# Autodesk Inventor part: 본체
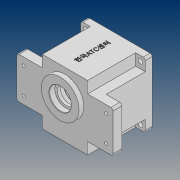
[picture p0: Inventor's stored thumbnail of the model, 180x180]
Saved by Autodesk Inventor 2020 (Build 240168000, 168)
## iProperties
Created: 2020-07
Part Number: 본체
Material: 일반
Document SubType Name: Modeling
Designer: PC312-
Density: 1 g/cm^3
Appearance: 기본값
Mass: 324.617 g
Surface Area: 793.597 cm^2
Volume: 324.617 cm^3
Author: PC312-
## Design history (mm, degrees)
sketch "스케치1"
  geometry: L1 (-47, 47)-(47, 47); L2 (47, 47)-(47, -47); L3 (47, -47)-(-47, -47); L4 (-47, -47)-(-47, 47); L5 (-47, 47)-(47, -47); L6 (47, 47)-(-47, -47); 1 further point
  constraints: 12 end point, 2 midpoint, 2 parallel, 1 horizontal, 1 perpendicular
  dimensions: "d0" = 94 distance of L2.end L3.end; "d1" = 94 distance of L1.end L2.end
extrude "돌출1" new body sketch "스케치1" stored distance "d2" = 80; taper "d3" = 0 deg
sketch "스케치2"
  geometry: C1 r 27.5 at (0, 11); 1 further point
  constraints: 1 centre point, 1 vertical alignment
  dimensions: "d4" = 55 diameter of C1; "d5" = 11 distance of point (0, 0) C1.centre
extrude "돌출2" join sketch "스케치2" distance "d6" = 7; taper "d7" = 0 deg
sketch "스케치3"
  geometry: L1 (-70, 30)-(70, 30); L2 (70, 30)-(70, -30); L3 (70, -30)-(-70, -30); L4 (-70, -30)-(-70, 30); L5 (-70, 30)-(70, -30); L6 (70, 30)-(-70, -30); 1 further point
  constraints: 12 end point, 2 midpoint, 2 parallel, 1 horizontal, 1 perpendicular
  dimensions: "d8" = 140 distance of L2.end L3.end; "d9" = 60 distance of L1.end L2.end
extrude "돌출3" join sketch "스케치3" distance "d10" = 13; taper "d11" = 0 deg
sketch "스케치4"
  geometry: L1 (47, 47)-(-47, 47) reference; L2 (33, 47)-(33, 30); L3 (47, 30)-(47, -30) reference; L4 (33, 30)-(47, 30); L5 (47, 30)-(47, 47) reference; L6 (33, 47)-(47, 47); L7 (47, 47)-(47, 29.432); 1 further point
  constraints: 8 end point, 2 point on line, 1 horizontal, 1 vertical
  dimensions: "d12" = 17 distance of L2.start L2.end; "d14" = 14 distance of L2.end L3.start
extrude "돌출4" cut sketch "스케치4" distance "d15" = 70; taper "d16" = 0 deg
sketch "스케치5"
  geometry: C1 r 3.5 at (-40, -40); C2 r 3.5 at (40, -40); C3 r 3.5 at (-40, 40); C4 r 3.5 at (40, 40); 1 further point
  constraints: 4 centre point
  dimensions: "d17" = 7 diameter of C1; "d18" = 7 diameter of C2; "d19" = 7 diameter of C3; "d20" = 7 diameter of C4; "d21" = 80 distance of C2.centre C4.centre; "d22" = 80 distance of C1.centre C3.centre; "d23" = 80 distance of C4.centre C3.centre; "d24" = 80 distance of C2.centre C1.centre; "d25" = 40 horizontal distance of C4.centre point (0, 0); "d26" = 40 horizontal distance of point (0, 0) C3.centre; "d27" = 40 horizontal distance of C2.centre point (0, 0); "d28" = 40 horizontal distance of C2.centre point (0, 0)
extrude "돌출5" cut sketch "스케치5" extent not by distance; stored distance "d29" = 0; taper "d30" = 0 deg
sketch "스케치6"
  geometry: 3 further points
  constraints: 1 vertical alignment
  dimensions: "d31" = 38 distance of point (-60, 19) point (-60, -19); "d32" = 19 vertical distance of point (-60, -19) point (0, 0); "d33" = 60 horizontal distance of point (-60, -19) point (0, 0)
hole "구멍1" sketch "스케치6" at (-60, -19), (-60, 19) diameter "d34" = 4.5; stored, may be unused: countersink angle "d38" = 90 deg, drill point angle "d40" = 118 deg; dims "d35" = 8, "d36" = 10, "d37" = 5, "d39" = 13
sketch "스케치7"
  geometry: C1 r 43 at (0, 0); 1 further point
  constraints: 1 centre point, 1 coincident
  dimensions: "d41" = 86 diameter of C1
extrude "돌출6" cut sketch "스케치7" distance "d42" = 9; taper "d43" = 0 deg
sketch "스케치8"
  geometry: C1 r 40 at (0, 0); 1 further point
  constraints: 1 centre point, 1 coincident
  dimensions: "d44" = 80 diameter of C1
extrude "돌출7" cut sketch "스케치8" distance "d45" = 62; taper "d46" = 0 deg
sketch "스케치9"
  geometry: A1 r 21 centre (0, 11) between (12.163, -6.119) and (-12.163, -6.119); A2 r 15 centre (0, -20) between (-11.584, -10.47) and (11.584, -10.47); A3 r 3 centre (-13.901, -8.565) between (-11.584, -10.47) and (-12.163, -6.119); A4 r 3 centre (13.901, -8.565) between (12.163, -6.119) and (11.584, -10.47); 1 further point
  constraints: 8 point on circle, 4 centre point, 4 tangent, 2 vertical alignment
  dimensions: "d47" = 42 diameter of A1; "d48" = 30 diameter of A2; "d49" = 11 distance of point (0, 0) A1.centre; "d50" = 20 distance of point (0, 0) A2.centre; "d51" = 6 diameter of A3; "d52" = 6 diameter of A4
extrude "돌출8" join sketch "스케치9" distance "d53" = 7; taper "d54" = 0 deg
sketch "스케치10"
  geometry: A1 r 36 centre (0, 0) between (36, 0) and (-36, 0); A2 r 4 centre (36, 0) between (36.19, 3.995) and (36.19, -3.995); A3 r 4 centre (-36, 0) between (-36.19, -3.995) and (-36.19, 3.995); A4 r 3 centre (36.333, 6.992) between (35.772, 4.045) and (39.279, 7.559); A5 r 3 centre (36.333, -6.992) between (39.279, -7.559) and (35.772, -4.045); A6 r 3 centre (-36.333, 6.992) between (-39.279, 7.559) and (-35.772, 4.045); A7 r 3 centre (-36.333, -6.992) between (-35.772, -4.045) and (-39.279, -7.559); A8 r 40 centre (0, 0) between (-39.279, 7.559) and (-39.279, -7.559) reference; 1 further point
  constraints: 26 point on circle, 8 tangent, 7 centre point, 2 horizontal alignment, 1 coincident
  dimensions: "d55" = 72 diameter of A1; "d56" = 8 diameter of A2; "d57" = 8 diameter of A3; "d58" = 6 diameter of A4; "d59" = 6 diameter of A5; "d60" = 6 diameter of A6; "d61" = 6 diameter of A7
extrude "돌출9" join sketch "스케치10" distance "d62" = 62; taper "d63" = 0 deg
sketch "스케치11"
  geometry: C1 r 17.5 at (0, 11); A1 r 21 centre (0, 11) between (12.163, -6.119) and (-12.163, -6.119) reference; 1 further point
  constraints: 1 centre point, 1 coincident
  dimensions: "d64" = 35 diameter of C1
extrude "돌출10" cut sketch "스케치11" distance "d65" = 10; taper "d66" = 0 deg
sketch "스케치12"
  geometry: C1 r 27.5 at (0, 0) reference; 2 further points
  constraints: 1 coincident
hole "구멍2" sketch "스케치12" at (0, 0) diameter "d67" = 25; stored, may be unused: countersink angle "d71" = 90 deg, drill point angle "d73" = 118 deg; dims "d68" = 8, "d69" = 32, "d70" = 8.3, "d72" = 13
sketch "스케치13"
  geometry: C1 r 11 at (0, -20); A1 r 15 centre (0, -20) between (-11.584, -10.47) and (11.584, -10.47) reference; 1 further point
  constraints: 1 centre point, 1 coincident
  dimensions: "d74" = 22 diameter of C1
extrude "돌출11" cut sketch "스케치13" distance "d75" = 7; taper "d76" = 0 deg
sketch "스케치14"
  geometry: C1 r 9.5 at (0, 0); A1 r 15 centre (0, 0) between (-11.584, 9.53) and (11.584, 9.53) reference; 1 further point
  constraints: 1 centre point, 1 coincident
  dimensions: "d77" = 19 diameter of C1
extrude "돌출12" cut sketch "스케치14" distance "d78" = 3; taper "d79" = 0 deg
sketch "스케치16"
  geometry: A1 r 4 centre (36, 0) between (36.19, 3.995) and (36.19, -3.995) reference; A2 r 4 centre (-36, 0) between (-36.19, -3.995) and (-36.19, 3.995) reference; 3 further points
  constraints: 2 coincident
hole "구멍3" sketch "스케치16" at (36, 0), (-36, 0) diameter "d80" = 3.242; stored, may be unused: countersink angle "d84" = 90 deg, drill point angle "d86" = 118 deg; dims "d81" = 7, "d82" = 32, "d83" = 8.3, "d85" = 9
chamfer "모따기1" distance "d87" = 0.8; stored, may be unused: second distance "d88" = 2, angle "d89" = 30 deg
chamfer "모따기2" distance "d90" = 1; stored, may be unused: second distance "d91" = 2, angle "d92" = 30 deg
fillet "모깎기1" dims "d93" = 3
fillet "모깎기2" dims "d94" = 3
node "작업 평면1"
sketch "스케치17"
  geometry: L1 (-77, 80)-(11, 80) reference; 2 further points
  constraints: 1 coincident, 1 other
  dimensions: "d96" = 40 distance from line of L1 point (-33, 40)
feature "엠보싱1" sketch "스케치17" dims "d0" = 94, "d1" = 94, "d97" = 0.5, "d98" = 0
node "솔리드1"
mirror "미러1"
mirror "미러2"
mirror "미러3"
feature "A9D066F2-1C7D-4E18-AEED-F7BC21143FA4" dims "d34" = 4.5, "d35" = 8, "d36" = 10, "d37" = 5, "d38" = 90 deg, "d39" = 13, "d40" = 118 deg
other parameters: "d95" = 0.5
